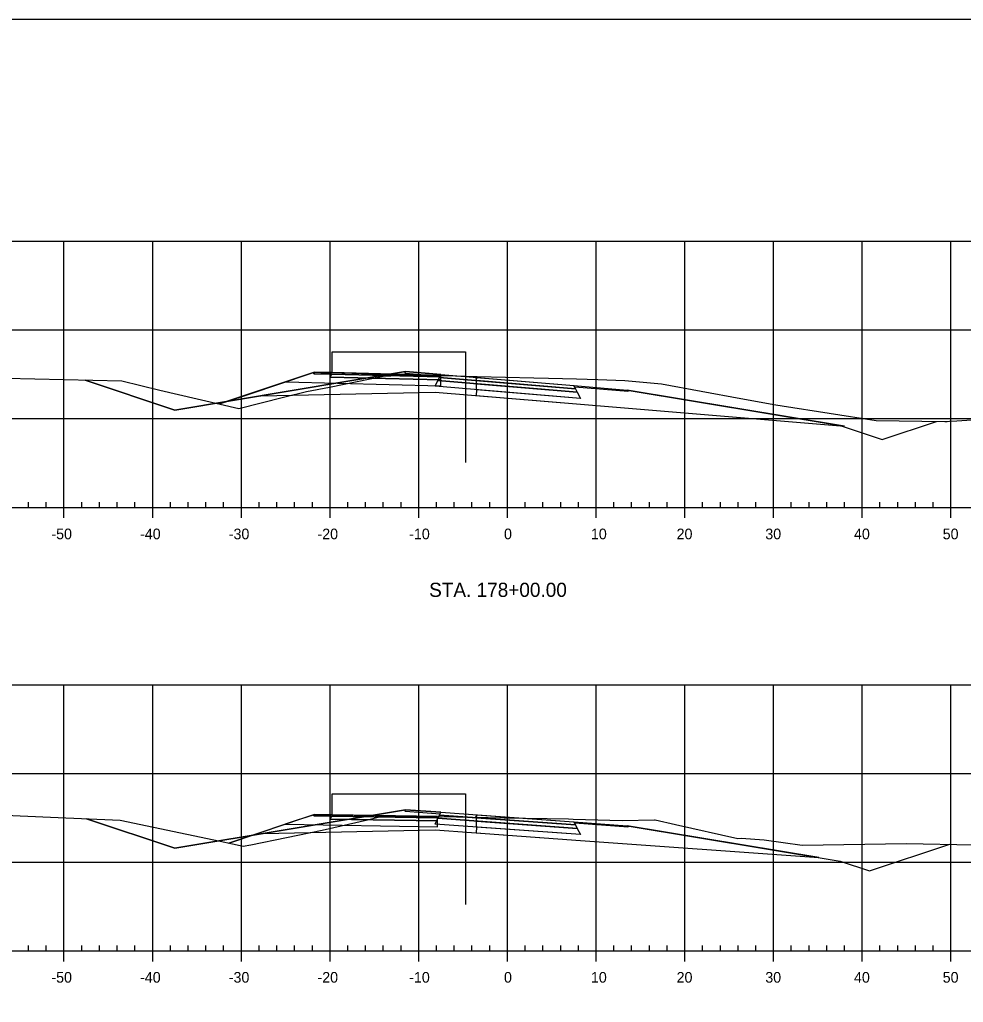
# Model space of a CAD drawing. Extents: x 659657 to 668193, y 633084 to 648639.
# Drawn here: x 666557.5 to 666663.9, y 643611.6 to 643722.4 of the extents above; entities that cross this region are included whole.
import ezdxf

# ---------------------------------------------------------------- set-up
doc = ezdxf.new("R2010")
doc.units = 0
for name, color, linetype in [('Default', 7, 'Continuous'), ('R_Axis', 7, 'Continuous'), ('R_Axis Annot', 7, 'Continuous'), ('R_Exist Surface', 7, 'Continuous'), ('R_Fin Surface', 7, 'Continuous'), ('R_Grid', 7, 'Continuous'), ('R_MOT_Stage 1B', 7, 'Continuous'), ('R_Sub Surface', 7, 'Continuous'), ('T_SIGNAL CONTROL CABINET', 7, 'Continuous'), ('TEMP_SIGNAL_HEAD_STAGE 5', 7, 'Continuous'), ('TEMP_SIGNAL_HEAD_STAGE4', 7, 'Continuous')]:
    doc.layers.add(name, color=color, linetype=linetype)

msp = doc.modelspace()

# ---------------------------------------------------------------- linework, layer by layer
for points in [[(666605, 643682.26), (666592.76, 643682.58), (666590.76, 643682.63), (666590.68, 643682.46), (666592.68, 643682.41), (666605, 643682.09)], [(666620.01, 643681.12), (666620.19, 643680.77), (666604.85, 643682.04), (666605.01, 643682.37)], [(666620.01, 643681.12), (666620.19, 643680.77), (666609.01, 643681.7), (666609.01, 643682.03)], [(666604.63, 643632.52), (666592.76, 643632.72), (666590.76, 643632.76), (666590.68, 643632.59), (666592.68, 643632.56), (666604.63, 643632.36)], [(666620.01, 643631.93), (666620.19, 643631.58), (666604.85, 643632.68), (666605.01, 643633.01)], [(666620.01, 643631.93), (666620.19, 643631.58), (666609.01, 643632.38), (666609.01, 643632.72)]]:
    msp.add_lwpolyline(points, close=True)
at = {"layer": 'Default'}
for points in [[(666564.9, 643681.73), (666575.01, 643678.36), (666575.01, 643678.36), (666601.01, 643682.7), (666605.01, 643682.37), (666620.01, 643681.12), (666626.01, 643680.62), (666650.01, 643676.62), (666654.76, 643675.04), (666660.87, 643677.08)], [(666580.04, 643679.05), (666582.72, 643679.94), (666587.52, 643681.54), (666589.61, 643682.24), (666590.76, 643682.63), (666591.48, 643682.61), (666592.76, 643682.58), (666597.16, 643682.46), (666605, 643682.26), (666605, 643682.26), (666605, 643682.26), (666605, 643682.26), (666605, 643682.26)], [(666608.87, 643682.16), (666609.01, 643681.87), (666609.01, 643682.03), (666620.01, 643681.12), (666626.01, 643680.62), (666650.01, 643676.62), (666654.76, 643675.04), (666660.87, 643677.08)], [(666565.05, 643632.28), (666575.01, 643628.96), (666575.01, 643628.96), (666601.01, 643633.29), (666605.01, 643633.01), (666620.01, 643631.93), (666626.01, 643631.49), (666650.01, 643627.49), (666653.33, 643626.39), (666662.38, 643629.41)], [(666581.09, 643629.53), (666584.43, 643630.65), (666587.43, 643631.65), (666589.23, 643632.25), (666590.76, 643632.76), (666591.86, 643632.74), (666592.76, 643632.72), (666595.22, 643632.68), (666604.63, 643632.52)], [(666608.96, 643632.45), (666609.01, 643632.55), (666609.01, 643632.72), (666620.01, 643631.93), (666626.01, 643631.49), (666650.01, 643627.49), (666653.33, 643626.39), (666662.38, 643629.41)]]:
    msp.add_lwpolyline(points, dxfattribs=at)
at = {"layer": 'R_Axis'}
for p, q in [((666562.51, 643666.19), (666562.51, 643668.59)), ((666572.51, 643666.19), (666572.51, 643668.59)), ((666582.51, 643666.19), (666582.51, 643668.59)), ((666592.51, 643666.19), (666592.51, 643668.59)), ((666602.51, 643666.19), (666602.51, 643668.59)), ((666612.51, 643666.19), (666612.51, 643668.59)), ((666622.51, 643666.19), (666622.51, 643668.59)), ((666632.51, 643666.19), (666632.51, 643668.59)), ((666642.51, 643666.19), (666642.51, 643668.59)), ((666652.51, 643666.19), (666652.51, 643668.59)), ((666662.51, 643666.19), (666662.51, 643668.59)), ((666558.51, 643667.39), (666558.51, 643667.99)), ((666560.51, 643667.39), (666560.51, 643667.99)), ((666564.51, 643667.39), (666564.51, 643667.99)), ((666566.51, 643667.39), (666566.51, 643667.99)), ((666568.51, 643667.39), (666568.51, 643667.99)), ((666570.51, 643667.39), (666570.51, 643667.99)), ((666574.51, 643667.39), (666574.51, 643667.99)), ((666576.51, 643667.39), (666576.51, 643667.99)), ((666578.51, 643667.39), (666578.51, 643667.99)), ((666580.51, 643667.39), (666580.51, 643667.99)), ((666584.51, 643667.39), (666584.51, 643667.99)), ((666586.51, 643667.39), (666586.51, 643667.99)), ((666588.51, 643667.39), (666588.51, 643667.99)), ((666590.51, 643667.39), (666590.51, 643667.99)), ((666594.51, 643667.39), (666594.51, 643667.99)), ((666596.51, 643667.39), (666596.51, 643667.99)), ((666598.51, 643667.39), (666598.51, 643667.99)), ((666600.51, 643667.39), (666600.51, 643667.99)), ((666604.51, 643667.39), (666604.51, 643667.99)), ((666606.51, 643667.39), (666606.51, 643667.99)), ((666608.51, 643667.39), (666608.51, 643667.99)), ((666610.51, 643667.39), (666610.51, 643667.99)), ((666614.51, 643667.39), (666614.51, 643667.99)), ((666616.51, 643667.39), (666616.51, 643667.99)), ((666618.51, 643667.39), (666618.51, 643667.99)), ((666620.51, 643667.39), (666620.51, 643667.99)), ((666624.51, 643667.39), (666624.51, 643667.99)), ((666626.51, 643667.39), (666626.51, 643667.99)), ((666628.51, 643667.39), (666628.51, 643667.99)), ((666630.51, 643667.39), (666630.51, 643667.99)), ((666634.51, 643667.39), (666634.51, 643667.99)), ((666636.51, 643667.39), (666636.51, 643667.99)), ((666638.51, 643667.39), (666638.51, 643667.99)), ((666640.51, 643667.39), (666640.51, 643667.99)), ((666644.51, 643667.39), (666644.51, 643667.99)), ((666646.51, 643667.39), (666646.51, 643667.99)), ((666648.51, 643667.39), (666648.51, 643667.99)), ((666650.51, 643667.39), (666650.51, 643667.99)), ((666654.51, 643667.39), (666654.51, 643667.99)), ((666656.51, 643667.39), (666656.51, 643667.99)), ((666658.51, 643667.39), (666658.51, 643667.99)), ((666660.51, 643667.39), (666660.51, 643667.99)), ((666462.51, 643667.39), (666762.51, 643667.39)), ((666558.51, 643617.39), (666558.51, 643617.99)), ((666560.51, 643617.39), (666560.51, 643617.99)), ((666562.51, 643616.19), (666562.51, 643618.59)), ((666564.51, 643617.39), (666564.51, 643617.99)), ((666566.51, 643617.39), (666566.51, 643617.99)), ((666568.51, 643617.39), (666568.51, 643617.99)), ((666570.51, 643617.39), (666570.51, 643617.99)), ((666572.51, 643616.19), (666572.51, 643618.59)), ((666574.51, 643617.39), (666574.51, 643617.99)), ((666576.51, 643617.39), (666576.51, 643617.99)), ((666578.51, 643617.39), (666578.51, 643617.99)), ((666580.51, 643617.39), (666580.51, 643617.99)), ((666582.51, 643616.19), (666582.51, 643618.59)), ((666584.51, 643617.39), (666584.51, 643617.99)), ((666586.51, 643617.39), (666586.51, 643617.99)), ((666588.51, 643617.39), (666588.51, 643617.99)), ((666590.51, 643617.39), (666590.51, 643617.99)), ((666592.51, 643616.19), (666592.51, 643618.59)), ((666594.51, 643617.39), (666594.51, 643617.99)), ((666596.51, 643617.39), (666596.51, 643617.99)), ((666598.51, 643617.39), (666598.51, 643617.99)), ((666600.51, 643617.39), (666600.51, 643617.99)), ((666602.51, 643616.19), (666602.51, 643618.59)), ((666604.51, 643617.39), (666604.51, 643617.99)), ((666606.51, 643617.39), (666606.51, 643617.99)), ((666608.51, 643617.39), (666608.51, 643617.99)), ((666610.51, 643617.39), (666610.51, 643617.99)), ((666612.51, 643616.19), (666612.51, 643618.59)), ((666614.51, 643617.39), (666614.51, 643617.99)), ((666616.51, 643617.39), (666616.51, 643617.99)), ((666618.51, 643617.39), (666618.51, 643617.99)), ((666620.51, 643617.39), (666620.51, 643617.99)), ((666622.51, 643616.19), (666622.51, 643618.59)), ((666624.51, 643617.39), (666624.51, 643617.99)), ((666626.51, 643617.39), (666626.51, 643617.99)), ((666628.51, 643617.39), (666628.51, 643617.99)), ((666630.51, 643617.39), (666630.51, 643617.99)), ((666632.51, 643616.19), (666632.51, 643618.59)), ((666634.51, 643617.39), (666634.51, 643617.99)), ((666636.51, 643617.39), (666636.51, 643617.99)), ((666638.51, 643617.39), (666638.51, 643617.99)), ((666640.51, 643617.39), (666640.51, 643617.99)), ((666642.51, 643616.19), (666642.51, 643618.59)), ((666644.51, 643617.39), (666644.51, 643617.99)), ((666646.51, 643617.39), (666646.51, 643617.99)), ((666648.51, 643617.39), (666648.51, 643617.99)), ((666650.51, 643617.39), (666650.51, 643617.99)), ((666652.51, 643616.19), (666652.51, 643618.59)), ((666654.51, 643617.39), (666654.51, 643617.99)), ((666656.51, 643617.39), (666656.51, 643617.99)), ((666658.51, 643617.39), (666658.51, 643617.99)), ((666660.51, 643617.39), (666660.51, 643617.99)), ((666662.51, 643616.19), (666662.51, 643618.59)), ((666462.51, 643617.39), (666762.51, 643617.39))]:
    msp.add_line(p, q, dxfattribs=at)
at = {"layer": 'R_Exist Surface'}
for points in [[(666552.66, 643682.02), (666569.03, 643681.64), (666573.3, 643680.61), (666582.23, 643678.54), (666587.26, 643679.82), (666589.85, 643680.45), (666592.45, 643680.96), (666598.51, 643682.17), (666600.23, 643682.25), (666601.28, 643682.32), (666603.59, 643682.28), (666605, 643682.26), (666605.63, 643682.24), (666606.65, 643682.22), (666609.09, 643682.15), (666615.48, 643681.98), (666617.15, 643681.95), (666620.28, 643681.9), (666622.68, 643681.81), (666625.75, 643681.7), (666626.98, 643681.58), (666629.86, 643681.3), (666638.82, 643679.68), (666642.78, 643678.94), (666643.49, 643678.84), (666654.09, 643677.17), (666661.83, 643677.06), (666662.09, 643677.06), (666662.35, 643677.09), (666663.17, 643677.14), (666667.71, 643677.46)], [(666544.78, 643633.17), (666561, 643632.44), (666568.84, 643632.13), (666580.13, 643629.76), (666581.5, 643629.45), (666582.71, 643629.19), (666583.57, 643629.35), (666591.62, 643630.97), (666596.74, 643632.16), (666598.24, 643632.53), (666598.85, 643632.52), (666601.78, 643632.55), (666603.95, 643632.52), (666604.63, 643632.52), (666606.76, 643632.49), (666612.15, 643632.39), (666619.4, 643632.25), (666619.91, 643632.23), (666621.29, 643632.2), (666625.44, 643632.07), (666629.07, 643632.14), (666629.17, 643632.15), (666631.44, 643631.63), (666638.49, 643630.06), (666638.84, 643630.07), (666641.44, 643629.9), (666645.74, 643629.29), (666657.5, 643629.5), (666665.06, 643629.35)]]:
    msp.add_lwpolyline(points, dxfattribs=at)
at = {"layer": 'R_Fin Surface'}
for points in [[(666605, 643682.09), (666592.68, 643682.41), (666592.52, 643682.08), (666605, 643681.76)], [(666604.85, 643682.04), (666620.19, 643680.77), (666620.38, 643680.38), (666604.67, 643681.68)], [(666609.01, 643681.7), (666620.19, 643680.77), (666620.38, 643680.38), (666609, 643681.32)], [(666604.63, 643632.36), (666592.68, 643632.56), (666592.51, 643632.23), (666604.63, 643632.02)], [(666604.85, 643632.68), (666620.19, 643631.58), (666620.38, 643631.19), (666604.67, 643632.32)], [(666609.01, 643632.38), (666620.19, 643631.58), (666620.38, 643631.19), (666609, 643632.01)]]:
    msp.add_lwpolyline(points, close=True, dxfattribs=at)
at = {"layer": 'R_Grid'}
for p, q in [((666462.51, 643697.39), (666762.51, 643697.39)), ((666562.51, 643667.39), (666562.51, 643697.39)), ((666572.51, 643667.39), (666572.51, 643697.39)), ((666582.51, 643667.39), (666582.51, 643697.39)), ((666592.51, 643667.39), (666592.51, 643697.39)), ((666602.51, 643667.39), (666602.51, 643697.39)), ((666612.51, 643667.39), (666612.51, 643697.39)), ((666622.51, 643667.39), (666622.51, 643697.39)), ((666632.51, 643667.39), (666632.51, 643697.39)), ((666642.51, 643667.39), (666642.51, 643697.39)), ((666652.51, 643667.39), (666652.51, 643697.39)), ((666662.51, 643667.39), (666662.51, 643697.39)), ((666462.51, 643687.39), (666762.51, 643687.39)), ((666462.51, 643677.39), (666762.51, 643677.39)), ((666462.51, 643667.39), (666762.51, 643667.39)), ((666462.51, 643647.39), (666762.51, 643647.39)), ((666562.51, 643617.39), (666562.51, 643647.39)), ((666572.51, 643617.39), (666572.51, 643647.39)), ((666582.51, 643617.39), (666582.51, 643647.39)), ((666592.51, 643617.39), (666592.51, 643647.39)), ((666602.51, 643617.39), (666602.51, 643647.39)), ((666612.51, 643617.39), (666612.51, 643647.39)), ((666622.51, 643617.39), (666622.51, 643647.39)), ((666632.51, 643617.39), (666632.51, 643647.39)), ((666642.51, 643617.39), (666642.51, 643647.39)), ((666652.51, 643617.39), (666652.51, 643647.39)), ((666662.51, 643617.39), (666662.51, 643647.39)), ((666462.51, 643637.39), (666762.51, 643637.39)), ((666462.51, 643627.39), (666762.51, 643627.39)), ((666462.51, 643617.39), (666762.51, 643617.39))]:
    msp.add_line(p, q, dxfattribs=at)
at = {"layer": 'R_MOT_Stage 1B'}
for points in [[(666592.76, 643682.58), (666592.76, 643684.93), (666607.76, 643684.93), (666607.76, 643672.44)], [(666592.76, 643632.72), (666592.76, 643635.08), (666607.76, 643635.08), (666607.76, 643622.59)]]:
    msp.add_lwpolyline(points, dxfattribs=at)
at = {"layer": 'R_Sub Surface'}
for points in [[(666601.01, 643682.7), (666584.7, 643679.98), (666604.35, 643680.37), (666620.73, 643679.01), (666650.5, 643676.54), (666626.01, 643680.62)], [(666609, 643680.66), (666608.99, 643679.99), (666620.73, 643679.01), (666650.5, 643676.54), (666626.01, 643680.62)], [(666601.01, 643633.29), (666584.96, 643630.62), (666604.35, 643631.01), (666620.73, 643629.83), (666647.63, 643627.89), (666626.01, 643631.49)], [(666609, 643631.34), (666608.99, 643630.67), (666620.73, 643629.83), (666647.63, 643627.89), (666626.01, 643631.49)]]:
    msp.add_lwpolyline(points, dxfattribs=at)
for points in [[(666605, 643681.76), (666592.52, 643682.08), (666592.68, 643682.41), (666605, 643682.09), (666592.68, 643682.41), (666590.68, 643682.46), (666590.76, 643682.63), (666587.52, 643681.54), (666605, 643681.09)], [(666604.67, 643681.68), (666620.38, 643680.38), (666620.73, 643679.68), (666604.35, 643681.04)], [(666609, 643681.32), (666620.38, 643680.38), (666620.73, 643679.68), (666609, 643680.66)], [(666604.63, 643632.02), (666592.51, 643632.23), (666592.68, 643632.56), (666604.63, 643632.36), (666592.68, 643632.56), (666590.68, 643632.59), (666590.76, 643632.76), (666587.43, 643631.65), (666604.63, 643631.35)], [(666604.67, 643632.32), (666620.38, 643631.19), (666620.73, 643630.5), (666604.35, 643631.67)], [(666609, 643632.01), (666620.38, 643631.19), (666620.73, 643630.5), (666609, 643631.34)]]:
    msp.add_lwpolyline(points, close=True, dxfattribs=at)
at = {"layer": 'T_SIGNAL CONTROL CABINET'}
msp.add_lwpolyline([(666452.51, 643502.39), (666792.51, 643502.39), (666792.51, 643722.39), (666452.51, 643722.39)], close=True, dxfattribs=at)
at = {"layer": 'TEMP_SIGNAL_HEAD_STAGE 5'}
for points in [[(666601.01, 643682.7), (666575.01, 643678.36), (666575.01, 643678.36), (666564.9, 643681.73)], [(666590.76, 643682.63), (666580.04, 643679.05)], [(666609.01, 643682.03), (666609.01, 643681.87), (666608.87, 643682.16)], [(666626.01, 643680.62), (666650.01, 643676.62), (666654.76, 643675.04), (666660.87, 643677.08)], [(666626.01, 643680.62), (666650.01, 643676.62), (666654.76, 643675.04), (666660.87, 643677.08)], [(666601.01, 643633.29), (666575.01, 643628.96), (666575.01, 643628.96), (666565.05, 643632.28)], [(666590.76, 643632.76), (666581.09, 643629.53)], [(666609.01, 643632.72), (666609.01, 643632.55), (666608.96, 643632.45)], [(666626.01, 643631.49), (666650.01, 643627.49), (666653.33, 643626.39), (666662.38, 643629.41)], [(666626.01, 643631.49), (666650.01, 643627.49), (666653.33, 643626.39), (666662.38, 643629.41)]]:
    msp.add_lwpolyline(points, dxfattribs=at)
at = {"layer": 'TEMP_SIGNAL_HEAD_STAGE4'}
for points in [[(666605.01, 643682.37), (666601.01, 643682.7), (666601.01, 643682.7), (666600.93, 643682.53), (666601.01, 643682.53), (666604.93, 643682.2)], [(666620.01, 643681.12), (666626.01, 643680.62), (666626.1, 643680.46), (666620.1, 643680.95)], [(666620.01, 643681.12), (666626.01, 643680.62), (666626.1, 643680.46), (666620.1, 643680.95)], [(666605.01, 643633.01), (666601.01, 643633.29), (666601.01, 643633.29), (666600.93, 643633.13), (666601.01, 643633.13), (666604.93, 643632.84)], [(666620.01, 643631.93), (666626.01, 643631.49), (666626.1, 643631.33), (666620.1, 643631.76)], [(666620.01, 643631.93), (666626.01, 643631.49), (666626.1, 643631.33), (666620.1, 643631.76)]]:
    msp.add_lwpolyline(points, close=True, dxfattribs=at)

# ---------------------------------------------------------------- texts
at = {"layer": 'R_Axis Annot'}
for s, height, p in [('-50', 1.2, (666561.09, 643663.79)), ('-40', 1.2, (666571.09, 643663.79)), ('-30', 1.2, (666581.09, 643663.79)), ('-20', 1.2, (666591.09, 643663.79)), ('-10', 1.2, (666601.43, 643663.79)), ('0', 1.2, (666612.12, 643663.79)), ('10', 1.2, (666621.92, 643663.79)), ('20', 1.2, (666631.58, 643663.79)), ('30', 1.2, (666641.58, 643663.79)), ('40', 1.2, (666651.58, 643663.79)), ('50', 1.2, (666661.58, 643663.79)), ('STA. 178+00.00', 1.6, (666603.68, 643657.29)), ('-50', 1.2, (666561.09, 643613.79)), ('-40', 1.2, (666571.09, 643613.79)), ('-30', 1.2, (666581.09, 643613.79)), ('-20', 1.2, (666591.09, 643613.79)), ('-10', 1.2, (666601.43, 643613.79)), ('0', 1.2, (666612.12, 643613.79)), ('10', 1.2, (666621.92, 643613.79)), ('20', 1.2, (666631.58, 643613.79)), ('30', 1.2, (666641.58, 643613.79)), ('40', 1.2, (666651.58, 643613.79)), ('50', 1.2, (666661.58, 643613.79))]:
    msp.add_text(s, height=height, dxfattribs=at).set_placement(p)

doc.saveas('drawing.dxf')
